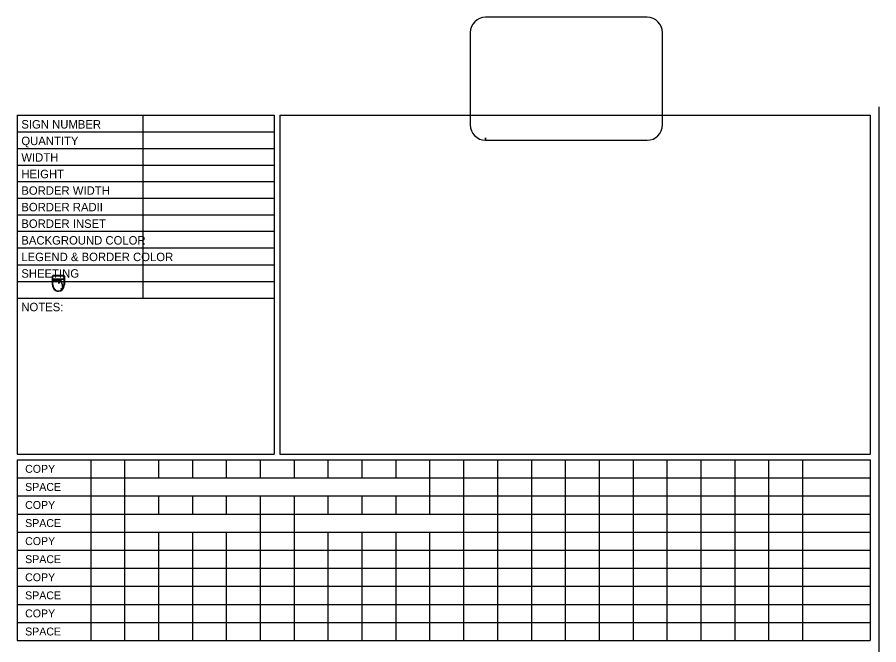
# Model space of a CAD drawing. Extents: x 10268197 to 10268511, y 2141503 to 2142677.
# Drawn here: x 10268318.5 to 10268394.7, y 2142322.7 to 2142378.2 of the extents above; entities that cross this region are included whole.
import ezdxf

# ---------------------------------------------------------------- set-up
doc = ezdxf.new("R2010")
doc.units = 0
for name, color, linetype in [('GSColorFill', 7, 'Continuous'), ('SheetBorder_dp', 7, 'Continuous'), ('SumBoxLines_dp', 7, 'Continuous'), ('SumBoxLinesMin_dp', 7, 'Continuous'), ('TextMisc', 7, 'Continuous')]:
    doc.layers.add(name, color=color, linetype=linetype)

msp = doc.modelspace()

# ---------------------------------------------------------------- linework, layer by layer
at = {"layer": 'GSColorFill'}
for p, q in [((10268374.225, 2142378.212), (10268359.932, 2142378.212)), ((10268358.571, 2142376.851), (10268358.571, 2142368.684)), ((10268375.587, 2142368.684), (10268375.587, 2142376.851)), ((10268359.932, 2142367.322), (10268359.932, 2142367.549)), ((10268359.934, 2142367.549), (10268359.934, 2142367.322)), ((10268359.934, 2142367.322), (10268374.225, 2142367.322))]:
    msp.add_line(p, q, dxfattribs=at)
for points in [[(10268321.597, 2142355.303), (10268321.597, 2142354.516)], [(10268321.597, 2142354.516), (10268321.597, 2142355.303)], [(10268321.613, 2142355.301), (10268321.613, 2142354.516)], [(10268322.615, 2142355.299), (10268322.615, 2142355.033), (10268321.635, 2142355.033), (10268321.635, 2142355.299)], [(10268321.635, 2142354.516), (10268321.635, 2142355.009), (10268322.615, 2142355.009), (10268322.615, 2142354.516)], [(10268322.595, 2142355.361), (10268321.655, 2142355.361)], [(10268321.655, 2142355.361), (10268322.595, 2142355.361)], [(10268321.658, 2142355.32), (10268322.125, 2142355.32), (10268322.125, 2142355.344), (10268321.656, 2142355.344)], [(10268321.684, 2142354.957), (10268321.685, 2142354.955)], [(10268321.972, 2142354.905), (10268322.247, 2142354.873)], [(10268322.268, 2142354.895), (10268321.98, 2142354.928)], [(10268322.594, 2142355.344), (10268322.125, 2142355.344), (10268322.125, 2142355.32), (10268322.593, 2142355.32)], [(10268322.318, 2142354.895), (10268322.33, 2142354.891)], [(10268322.334, 2142354.914), (10268322.325, 2142354.918)], [(10268322.637, 2142354.516), (10268322.637, 2142355.301)], [(10268322.654, 2142354.516), (10268322.654, 2142355.303)], [(10268322.654, 2142355.303), (10268322.654, 2142354.516)], [(10268321.71, 2142354.881), (10268321.711, 2142354.881)], [(10268321.712, 2142354.881), (10268321.713, 2142354.882)], [(10268322.169, 2142354.653), (10268322.189, 2142354.662)], [(10268322.284, 2142354.866), (10268322.282, 2142354.868)], [(10268322.309, 2142354.869), (10268322.31, 2142354.871)], [(10268322.349, 2142354.188), (10268322.328, 2142354.183)], [(10268322.337, 2142354.865), (10268322.359, 2142354.759)], [(10268322.381, 2142354.764), (10268322.358, 2142354.871)], [(10268322.387, 2142354.168), (10268322.377, 2142354.164)], [(10268322.385, 2142354.142), (10268322.402, 2142354.149)], [(10268322.394, 2142354.692), (10268322.405, 2142354.672)], [(10268322.425, 2142354.683), (10268322.414, 2142354.702)], [(10268322.417, 2142354.637), (10268322.444, 2142354.599)], [(10268322.462, 2142354.612), (10268322.434, 2142354.652)], [(10268322.451, 2142354.57), (10268322.461, 2142354.525)], [(10268322.482, 2142354.53), (10268322.472, 2142354.575)], [(10268322.125, 2142353.969), (10268322.125, 2142353.993)], [(10268322.125, 2142353.993), (10268322.125, 2142353.969), (10268322.125, 2142353.969)], [(10268322.125, 2142353.952), (10268322.125, 2142353.952)], [(10268322.125, 2142353.952), (10268322.125, 2142353.952)], [(10268322.125, 2142353.952), (10268322.125, 2142353.952)]]:
    msp.add_lwpolyline(points, dxfattribs=at)
for centre, start, end in [((10268359.932, 2142376.851), 90, 180), ((10268374.225, 2142376.851), 0, 90), ((10268359.932, 2142368.684), 180, 270), ((10268374.225, 2142368.684), 270, 0)]:
    msp.add_arc(centre, 1.361, start, end, dxfattribs=at)
for centre, major_axis, start_param, end_param in [((10268321.662, 2142355.291), (0, 0.0703), 0.098213, 1.408003), ((10268321.662, 2142355.291), (0, 0.0705), 0.098082, 1.408221), ((10268321.662, 2142355.291), (0, 0.0529), 0.11327, 1.383001), ((10268321.662, 2142355.291), (0, 0.0294), 0.152033, 1.318544), ((10268322.03, 2142354.81), (0, 0.418), 1.148552, 1.171978), ((10268321.671, 2142354.972), (0, 0.00205), 1.350308, 3.382945), ((10268321.672, 2142354.967), (0, 0.0033), 5.257186, 6.472249), ((10268321.653, 2142354.998), (0, 0.026), 4.051262, 4.587994), ((10268321.635, 2142354.936), (0, 0.0535), 5.170612, 5.366939), ((10268322.102, 2142358.792), (0, 3.824), 3.0228, 3.102998), ((10268321.681, 2142354.96), (0, 0.00167), 1.876358, 3.458947), ((10268321.691, 2142354.895), (0, 0.0123), 0.633597, 2.648042), ((10268321.682, 2142354.957), (0, 0.0023), 5.006675, 6.675737), ((10268321.688, 2142354.956), (0, 0.00328), 1.878733, 3.108176), ((10268321.682, 2142354.91), (0, 0.00646), 3.672662, 4.871849), ((10268321.687, 2142354.944), (0, 0.00855), 5.256742, 6.115579), ((10268321.781, 2142354.908), (0, 0.0999), 1.186151, 1.539742), ((10268321.691, 2142354.946), (0, 0.00333), 4.486807, 5.309085), ((10268321.687, 2142354.944), (0, 0.032), 5.272311, 5.523753), ((10268322.102, 2142358.792), (0, 3.848), 3.031956, 3.0986), ((10268321.781, 2142354.908), (0, 0.0764), 1.174629, 1.522814), ((10268321.682, 2142354.91), (0, 0.03), 4.660636, 4.76546), ((10268321.921, 2142355.496), (0, 0.629), 2.775496, 2.836), ((10268321.691, 2142354.946), (0, 0.0268), 4.38027, 5.281838), ((10268321.759, 2142354.976), (0, 0.081), 2.935797, 3.111869), ((10268321.692, 2142354.343), (0, 0.556), 6.084521, 6.158258), ((10268321.979, 2142354.965), (0, 0.0374), 2.044108, 2.116391), ((10268321.994, 2142354.948), (0, 0.0489), 1.626511, 2.63302), ((10268321.954, 2142354.964), (0, 0.012), 4.739475, 5.22955), ((10268321.979, 2142354.965), (0, 0.0139), 1.562078, 2.226686), ((10268321.964, 2142354.951), (0, 0.00667), 4.461638, 5.646624), ((10268321.994, 2142354.948), (0, 0.0254), 1.523898, 2.474336), ((10268322.276, 2142354.893), (0, 0.00913), 1.352418, 2.01063), ((10268322.321, 2142354.908), (0, 0.0351), 1.15727, 1.990189), ((10268322.292, 2142354.925), (0, 0.00308), 2.554355, 4.582696), ((10268322.273, 2142354.888), (0, 0.0194), 4.289312, 5.031813), ((10268322.303, 2142354.922), (0, 0.00883), 0.407393, 1.224717), ((10268322.301, 2142354.926), (0, 0.00399), 5.525274, 6.621403), ((10268322.328, 2142354.956), (0, 0.0373), 2.364476, 2.623448), ((10268322.312, 2142354.927), (0, 0.0037), 2.763735, 3.701166), ((10268322.273, 2142354.888), (0, 0.0429), 4.289312, 4.979338), ((10268322.319, 2142354.904), (0, 0.00845), 2.088134, 3.055358), ((10268322.315, 2142354.921), (0, 0.0032), 5.726467, 6.786368), ((10268322.309, 2142354.909), (0, 0.0168), 5.307679, 5.799127), ((10268322.32, 2142354.887), (0, 0.0308), 6.107601, 6.199828), ((10268322.338, 2142354.938), (0, 0.0241), 2.956314, 3.451659), ((10268322.347, 2142354.906), (0, 0.00977), 4.497594, 6.497324), ((10268322.419, 2142354.892), (0, 0.0684), 1.39821, 1.880074), ((10268322.589, 2142355.291), (0, 0.0294), 4.964641, 6.131152), ((10268322.589, 2142355.291), (0, 0.0529), 4.900184, 6.169915), ((10268322.589, 2142355.291), (0, 0.0703), 4.875182, 6.184972), ((10268322.589, 2142355.291), (0, 0.0705), 4.874965, 6.185103), ((10268322.125, 2142354.516), (0, 0.564), 1.570796, 3.141593), ((10268322.125, 2142354.516), (0, 0.564), 1.570796, 3.141593), ((10268322.125, 2142354.516), (0, 0.546), 1.570796, 3.141593), ((10268322.125, 2142354.516), (0, 0.523), 1.570796, 3.141593), ((10268321.696, 2142354.92), (0, 0.0377), 2.867281, 3.188718), ((10268321.695, 2142354.809), (0, 0.0733), 6.061742, 6.254182), ((10268321.711, 2142354.881), (0, 0.000638), 2.840072, 4.276704), ((10268321.713, 2142354.882), (0, 0.000524), 5.987968, 7.518423), ((10268321.921, 2142355.496), (0, 0.652), 2.795567, 2.837701), ((10268321.759, 2142354.976), (0, 0.105), 2.923962, 3.100366), ((10268321.692, 2142354.343), (0, 0.533), 6.086214, 6.156313), ((10268321.803, 2142354.918), (0, 0.0544), 2.874985, 3.359529), ((10268321.803, 2142354.918), (0, 0.0309), 2.852504, 3.366789), ((10268321.824, 2142354.81), (0, 0.0792), 6.040706, 6.480942), ((10268321.824, 2142354.81), (0, 0.0557), 6.026184, 6.476458), ((10268321.812, 2142354.704), (0, 0.161), 5.697067, 6.119013), ((10268321.812, 2142354.704), (0, 0.185), 5.684781, 6.113431), ((10268322.014, 2142354.969), (0, 0.181), 2.375, 2.467209), ((10268321.923, 2142354.808), (0, 0.0255), 0.964156, 2.090382), ((10268321.907, 2142354.797), (0, 0.00569), 1.939097, 3.308145), ((10268321.905, 2142354.822), (0, 0.00159), 5.485297, 7.704353), ((10268321.904, 2142354.82), (0, 0.0041), 4.221459, 5.929721), ((10268321.927, 2142354.812), (0, 0.0215), 1.284916, 1.908092), ((10268321.905, 2142354.816), (0, 0.0121), 4.628672, 6.022596), ((10268321.911, 2142354.807), (0, 0.00423), 2.162887, 4.05091), ((10268321.893, 2142354.894), (0, 0.104), 3.297928, 3.510473), ((10268322.014, 2142354.969), (0, 0.157), 2.362414, 2.445308), ((10268321.894, 2142354.813), (0, 0.0234), 4.312458, 4.790361), ((10268321.905, 2142354.816), (0, 0.0356), 4.927168, 5.844494), ((10268321.938, 2142354.774), (0, 0.0259), 6.114599, 6.726558), ((10268321.949, 2142354.913), (0, 0.09), 3.002553, 3.788583), ((10268321.949, 2142354.913), (0, 0.113), 3.077286, 3.764777), ((10268322.014, 2142354.812), (0, 0.0327), 0.291413, 0.478416), ((10268322.03, 2142354.83), (0, 0.0298), 1.091914, 1.118585), ((10268322.04, 2142354.826), (0, 0.041), 6.01566, 7.397045), ((10268322.014, 2142354.812), (0, 0.00922), 5.412655, 6.623003), ((10268322.029, 2142354.824), (0, 0.0104), 2.169624, 2.636557), ((10268322.03, 2142354.83), (0, 0.00627), 1.057989, 2.418777), ((10268322.026, 2142354.817), (0, 0.00291), 2.447997, 4.324956), ((10268322.04, 2142354.826), (0, 0.0175), 5.90331, 7.414322), ((10268322.022, 2142354.82), (0, 0.00757), 4.18924, 5.624255), ((10268322.05, 2142354.847), (0, 0.00632), 2.333666, 3.623187), ((10268322.057, 2142354.838), (0, 0.0282), 6.008573, 6.53107), ((10268322.057, 2142354.838), (0, 0.00472), 6.020224, 7.210209), ((10268322.033, 2142354.75), (0, 0.0962), 5.382216, 5.999852), ((10268322.033, 2142354.75), (0, 0.12), 5.371864, 6.001104), ((10268322.032, 2142354.762), (0, 0.0905), 5.020599, 5.276447), ((10268322.143, 2142354.806), (0, 0.0366), 2.049296, 2.415522), ((10268322.106, 2142354.763), (0, 0.0216), 4.723898, 5.514452), ((10268322.032, 2142354.762), (0, 0.114), 5.043581, 5.287393), ((10268322.125, 2142354.516), (0, 0.546), 3.14161, 4.712389), ((10268322.125, 2142354.516), (0, 0.523), 3.141611, 4.712389), ((10268322.125, 2142354.516), (0, 0.564), 3.141609, 4.712389), ((10268322.125, 2142354.516), (0, 0.564), 3.141609, 4.712389), ((10268322.213, 2142354.773), (0, 0.0926), 1.679569, 1.877594), ((10268322.148, 2142354.753), (0, 0.0211), 1.926422, 2.617636), ((10268322.143, 2142354.806), (0, 0.0132), 2.155604, 2.437858), ((10268322.106, 2142354.763), (0, 0.0451), 4.755633, 5.530169), ((10268322.119, 2142354.704), (0, 0.0371), 4.912404, 5.681954), ((10268322.213, 2142354.773), (0, 0.0691), 1.691953, 1.850237), ((10268322.119, 2142354.704), (0, 0.0606), 4.870438, 5.69492), ((10268322.197, 2142354.713), (0, 0.0466), 1.603254, 2.056889), ((10268322.09, 2142354.654), (0, 0.0815), 4.999681, 5.181626), ((10268322.17, 2142354.664), (0, 0.00829), 1.147713, 2.022718), ((10268322.152, 2142354.673), (0, 0.0125), 4.286383, 5.097358), ((10268322.152, 2142354.645), (0, 0.0191), 5.101976, 5.610981), ((10268322.197, 2142354.713), (0, 0.0231), 1.542583, 2.06345), ((10268322.09, 2142354.654), (0, 0.105), 5.008447, 5.183955), ((10268322.152, 2142354.673), (0, 0.036), 4.58555, 5.059156), ((10268322.152, 2142354.645), (0, 0.0426), 5.101976, 5.271031), ((10268322.272, 2142354.871), (0, 0.0263), 1.495786, 3.039166), ((10268322.188, 2142354.874), (0, 0.0869), 4.732247, 4.878022), ((10268322.262, 2142354.875), (0, 0.00805), 4.379744, 4.814874), ((10268322.272, 2142354.871), (0, 0.00285), 1.109885, 3.045896), ((10268322.277, 2142354.926), (0, 0.0809), 3.036263, 3.109566), ((10268322.277, 2142354.926), (0, 0.0574), 3.035408, 3.204096), ((10268322.285, 2142354.866), (0, 0.0242), 2.680355, 4.018837), ((10268322.28, 2142354.865), (0, 0.00354), 5.664697, 6.296132), ((10268322.285, 2142354.866), (0, 0.000707), 2.226104, 4.018837), ((10268322.282, 2142354.868), (0, 0.00364), 4.143687, 4.652253), ((10268322.32, 2142354.862), (0, 0.0367), 1.060493, 1.42239), ((10268322.293, 2142354.86), (0, 0.0137), 3.974032, 4.188492), ((10268322.282, 2142354.868), (0, 0.0271), 4.143687, 4.589576), ((10268322.32, 2142354.862), (0, 0.0132), 1.060493, 1.394015), ((10268322.377, 2142354.195), (0, 0.0543), 1.791653, 2.340122), ((10268322.338, 2142354.938), (0, 0.0476), 2.956314, 3.025542), ((10268322.419, 2142354.892), (0, 0.0919), 1.581121, 1.86815), ((10268322.351, 2142354.171), (0, 0.0176), 2.46822, 2.97436), ((10268322.345, 2142354.141), (0, 0.0125), 5.314558, 6.021061), ((10268322.377, 2142354.195), (0, 0.0308), 1.791653, 2.227493), ((10268322.345, 2142354.141), (0, 0.036), 5.376414, 6.007417), ((10268322.362, 2142354.15), (0, 0.00715), 1.799944, 2.906604), ((10268322.41, 2142354.769), (0, 0.0552), 1.756608, 2.347825), ((10268322.373, 2142354.174), (0, 0.0338), 2.704263, 3.531223), ((10268322.373, 2142354.174), (0, 0.0103), 2.98946, 3.543074), ((10268322.302, 2142354.661), (0, 0.103), 5.016392, 5.452977), ((10268322.41, 2142354.769), (0, 0.0317), 1.744904, 2.358794), ((10268322.409, 2142354.15), (0, 0.0301), 5.78233, 7.207903), ((10268322.302, 2142354.661), (0, 0.126), 5.037317, 5.457008), ((10268322.401, 2142354.151), (0, 0.00205), 3.416847, 4.470626), ((10268322.409, 2142354.15), (0, 0.00661), 5.753294, 7.753434), ((10268322.39, 2142354.664), (0, 0.0174), 4.762949, 5.1373), ((10268322.45, 2142354.668), (0, 0.0467), 1.627095, 2.292298), ((10268322.439, 2142354.21), (0, 0.0607), 2.662545, 2.881892), ((10268322.439, 2142354.21), (0, 0.0373), 2.671152, 2.787623), ((10268322.426, 2142354.162), (0, 0.0111), 2.983509, 3.299677), ((10268322.39, 2142354.664), (0, 0.0409), 4.76521, 5.169372), ((10268322.485, 2142353.84), (0, 0.34), 0.131385, 0.184159), ((10268322.485, 2142353.84), (0, 0.317), 0.127189, 0.195375), ((10268322.45, 2142354.668), (0, 0.0232), 1.628927, 2.328642), ((10268322.435, 2142354.21), (0, 0.0339), 3.405622, 3.421225), ((10268322.424, 2142354.584), (0, 0.0255), 4.794307, 5.332356), ((10268322.483, 2142354.16), (0, 0.0455), 1.014577, 1.160734), ((10268322.491, 2142354.194), (0, 0.049), 1.41458, 1.781645), ((10268322.519, 2142354.188), (0, 0.0794), 0.819897, 1.393572), ((10268322.435, 2142354.21), (0, 0.0574), 3.374432, 3.63571), ((10268322.543, 2142354.595), (0, 0.102), 1.656393, 1.820063), ((10268322.457, 2142354.165), (0, 0.00633), 3.821556, 4.442761), ((10268322.519, 2142354.535), (0, 0.0626), 1.731328, 2.298174), ((10268322.424, 2142354.584), (0, 0.0489), 4.795389, 5.336514), ((10268322.483, 2142354.16), (0, 0.022), 0.796146, 1.41392), ((10268322.485, 2142354.223), (0, 0.0286), 0.515561, 0.875133), ((10268322.491, 2142354.194), (0, 0.0255), 1.423525, 1.922114), ((10268322.519, 2142354.188), (0, 0.0559), 0.804456, 1.388824), ((10268322.46, 2142354.181), (0, 0.0105), 4.101497, 5.116348), ((10268322.543, 2142354.595), (0, 0.0784), 1.65682, 1.82178), ((10268322.641, 2142354.268), (0, 0.181), 1.336714, 1.678883), ((10268322.473, 2142354.492), (0, 0.00243), 4.321398, 5.522959), ((10268321.814, 2142354.399), (0, 0.711), 4.587168, 4.842218), ((10268322.519, 2142354.535), (0, 0.0391), 1.711025, 2.288429), ((10268322.485, 2142354.223), (0, 0.00515), 0.505292, 0.959827), ((10268322.481, 2142354.231), (0, 0.00426), 3.85142, 4.724901), ((10268322.505, 2142354.233), (0, 0.0223), 1.391226, 1.671625), ((10268322.492, 2142354.243), (0, 0.00793), 0.616902, 1.430067), ((10268322.21, 2142354.259), (0, 0.294), 4.638315, 4.661489), ((10268322.49, 2142354.223), (0, 0.00329), 0.723397, 2.164197), ((10268322.487, 2142354.244), (0, 0.0061), 5.021411, 6.053889), ((10268322.479, 2142354.233), (0, 0.0123), 4.104143, 4.720111), ((10268322.49, 2142354.222), (0, 0.00233), 1.92196, 4.222615), ((10268322.647, 2142354.208), (0, 0.169), 1.349215, 1.424914), ((10268322.473, 2142354.492), (0, 0.0259), 4.682902, 5.462261), ((10268322.641, 2142354.268), (0, 0.158), 1.328956, 1.760151), ((10268322.472, 2142354.235), (0, 0.0249), 4.100878, 4.619123), ((10268322.479, 2142354.236), (0, 0.0177), 4.523068, 4.807624), ((10268321.814, 2142354.399), (0, 0.735), 4.585352, 4.838269)]:
    msp.add_ellipse(centre, major_axis=major_axis, ratio=0.937499, start_param=start_param, end_param=end_param, dxfattribs=at)
at = {"layer": 'SheetBorder_dp'}
msp.add_line((10268394.73, 2142370.281), (10268394.73, 2142274.281), dxfattribs=at)
at = {"layer": 'SumBoxLines_dp'}
for p, q in [((10268318.48, 2142369.531), (10268318.48, 2142339.531)), ((10268318.48, 2142369.531), (10268341.23, 2142369.531)), ((10268329.598, 2142369.527), (10268329.598, 2142353.344)), ((10268341.23, 2142369.531), (10268341.23, 2142339.531)), ((10268341.73, 2142369.531), (10268341.73, 2142339.531)), ((10268341.73, 2142369.531), (10268393.98, 2142369.531)), ((10268393.98, 2142369.531), (10268393.98, 2142339.531)), ((10268318.48, 2142368.065), (10268341.23, 2142368.065)), ((10268318.48, 2142366.59), (10268341.23, 2142366.59)), ((10268318.48, 2142365.124), (10268341.23, 2142365.124)), ((10268318.48, 2142363.658), (10268341.23, 2142363.658)), ((10268318.48, 2142362.192), (10268341.23, 2142362.192)), ((10268318.48, 2142360.726), (10268341.23, 2142360.726)), ((10268318.48, 2142359.261), (10268341.23, 2142359.261)), ((10268318.48, 2142357.785), (10268341.23, 2142357.785)), ((10268318.48, 2142356.28), (10268341.23, 2142356.28)), ((10268318.479, 2142354.812), (10268341.23, 2142354.812)), ((10268318.478, 2142353.344), (10268341.229, 2142353.344)), ((10268318.48, 2142339.531), (10268341.23, 2142339.531)), ((10268318.48, 2142339.031), (10268393.98, 2142339.031)), ((10268318.48, 2142339.031), (10268318.48, 2142323.031)), ((10268324.98, 2142339.031), (10268324.98, 2142323.031)), ((10268327.98, 2142339.031), (10268327.98, 2142323.031)), ((10268330.98, 2142339.031), (10268330.98, 2142337.431)), ((10268333.98, 2142339.031), (10268333.98, 2142337.431)), ((10268336.98, 2142339.031), (10268336.98, 2142337.431)), ((10268339.98, 2142339.031), (10268339.98, 2142337.431)), ((10268341.73, 2142339.531), (10268393.98, 2142339.531)), ((10268342.98, 2142339.031), (10268342.98, 2142337.431)), ((10268345.98, 2142339.031), (10268345.98, 2142337.431)), ((10268348.98, 2142339.031), (10268348.98, 2142337.431)), ((10268351.98, 2142339.031), (10268351.98, 2142337.431)), ((10268354.98, 2142339.031), (10268354.98, 2142337.431)), ((10268357.98, 2142339.031), (10268357.98, 2142337.431)), ((10268360.98, 2142339.031), (10268360.98, 2142335.831)), ((10268363.98, 2142339.031), (10268363.98, 2142335.831)), ((10268366.98, 2142339.031), (10268366.98, 2142335.831)), ((10268369.98, 2142339.031), (10268369.98, 2142335.831)), ((10268372.98, 2142339.031), (10268372.98, 2142337.431)), ((10268375.98, 2142339.031), (10268375.98, 2142337.431)), ((10268378.98, 2142339.031), (10268378.98, 2142337.431)), ((10268381.98, 2142339.031), (10268381.98, 2142337.431)), ((10268384.98, 2142339.031), (10268384.98, 2142337.431)), ((10268387.98, 2142339.031), (10268387.98, 2142337.431)), ((10268393.98, 2142339.031), (10268393.98, 2142323.031)), ((10268354.98, 2142337.431), (10268354.98, 2142334.231)), ((10268357.98, 2142337.431), (10268357.98, 2142332.631)), ((10268372.98, 2142337.431), (10268372.98, 2142323.031)), ((10268375.98, 2142337.431), (10268375.98, 2142323.031)), ((10268378.98, 2142337.431), (10268378.98, 2142331.031)), ((10268381.98, 2142337.431), (10268381.98, 2142331.031)), ((10268384.98, 2142337.431), (10268384.98, 2142331.031)), ((10268387.98, 2142337.431), (10268387.98, 2142323.031)), ((10268318.48, 2142335.831), (10268393.98, 2142335.831)), ((10268330.98, 2142335.831), (10268330.98, 2142334.231)), ((10268333.98, 2142335.831), (10268333.98, 2142334.231)), ((10268336.98, 2142335.831), (10268336.98, 2142334.231)), ((10268339.98, 2142335.831), (10268339.98, 2142332.631)), ((10268342.98, 2142335.831), (10268342.98, 2142332.631)), ((10268345.98, 2142335.831), (10268345.98, 2142334.231)), ((10268348.98, 2142335.831), (10268348.98, 2142334.231)), ((10268351.98, 2142335.831), (10268351.98, 2142334.231)), ((10268360.98, 2142335.831), (10268360.98, 2142332.631)), ((10268363.98, 2142335.831), (10268363.98, 2142332.631)), ((10268366.98, 2142335.831), (10268366.98, 2142331.031)), ((10268369.98, 2142335.831), (10268369.98, 2142331.031)), ((10268318.48, 2142332.631), (10268393.98, 2142332.631)), ((10268330.98, 2142332.631), (10268330.98, 2142329.431)), ((10268333.98, 2142332.631), (10268333.98, 2142329.431)), ((10268336.98, 2142332.631), (10268336.98, 2142329.431)), ((10268339.98, 2142332.631), (10268339.98, 2142329.431)), ((10268342.98, 2142332.631), (10268342.98, 2142329.431)), ((10268345.98, 2142332.631), (10268345.98, 2142329.431)), ((10268348.98, 2142332.631), (10268348.98, 2142329.431)), ((10268351.98, 2142332.631), (10268351.98, 2142329.431)), ((10268354.98, 2142332.631), (10268354.98, 2142323.031)), ((10268357.98, 2142332.631), (10268357.98, 2142323.031)), ((10268360.98, 2142332.631), (10268360.98, 2142323.031)), ((10268363.98, 2142332.631), (10268363.98, 2142323.031)), ((10268366.98, 2142331.031), (10268366.98, 2142323.031)), ((10268369.98, 2142331.031), (10268369.98, 2142323.031)), ((10268378.98, 2142331.031), (10268378.98, 2142323.031)), ((10268381.98, 2142331.031), (10268381.98, 2142323.031)), ((10268384.98, 2142331.031), (10268384.98, 2142323.031)), ((10268318.48, 2142329.431), (10268393.98, 2142329.431)), ((10268330.98, 2142329.431), (10268330.98, 2142323.031)), ((10268333.98, 2142329.431), (10268333.98, 2142323.031)), ((10268336.98, 2142329.431), (10268336.98, 2142326.231)), ((10268339.98, 2142329.431), (10268339.98, 2142326.231)), ((10268342.98, 2142329.431), (10268342.98, 2142326.231)), ((10268345.98, 2142329.431), (10268345.98, 2142326.231)), ((10268348.98, 2142329.431), (10268348.98, 2142323.031)), ((10268351.98, 2142329.431), (10268351.98, 2142323.031)), ((10268318.48, 2142326.231), (10268393.98, 2142326.231)), ((10268336.98, 2142326.231), (10268336.98, 2142323.031)), ((10268339.98, 2142326.231), (10268339.98, 2142323.031)), ((10268342.98, 2142326.231), (10268342.98, 2142323.031)), ((10268345.98, 2142326.231), (10268345.98, 2142323.031)), ((10268318.48, 2142323.031), (10268393.98, 2142323.031))]:
    msp.add_line(p, q, dxfattribs=at)
at = {"layer": 'SumBoxLinesMin_dp'}
for p, q in [((10268318.48, 2142337.431), (10268393.98, 2142337.431)), ((10268318.48, 2142334.231), (10268393.98, 2142334.231)), ((10268318.48, 2142331.031), (10268393.98, 2142331.031)), ((10268318.48, 2142327.831), (10268393.98, 2142327.831)), ((10268318.48, 2142324.631), (10268393.98, 2142324.631))]:
    msp.add_line(p, q, dxfattribs=at)

# ---------------------------------------------------------------- texts
at = {"layer": 'TextMisc'}
for s, height, p in [('SIGN NUMBER', 0.74756, (10268318.842, 2142368.358)), ('QUANTITY', 0.7476, (10268318.842, 2142366.892)), ('WIDTH', 0.7476, (10268318.842, 2142365.427)), ('HEIGHT', 0.7476, (10268318.842, 2142363.961)), ('BORDER WIDTH', 0.74756, (10268318.842, 2142362.495)), ('BORDER RADII', 0.74756, (10268318.842, 2142361.029)), ('BORDER INSET', 0.74756, (10268318.842, 2142359.563)), ('BACKGROUND COLOR', 0.74756, (10268318.841, 2142358.086)), ('LEGEND & BORDER COLOR', 0.74756, (10268318.841, 2142356.62)), ('SHEETING', 0.7476, (10268318.841, 2142355.154)), ('NOTES:', 0.7476, (10268318.841, 2142352.183)), ('COPY', 0.7, (10268319.18, 2142337.881)), ('SPACE', 0.7, (10268319.18, 2142336.281)), ('COPY', 0.7, (10268319.18, 2142334.681)), ('SPACE', 0.7, (10268319.18, 2142333.081)), ('COPY', 0.7, (10268319.18, 2142331.481)), ('SPACE', 0.7, (10268319.18, 2142329.881)), ('COPY', 0.7, (10268319.18, 2142328.281)), ('SPACE', 0.7, (10268319.18, 2142326.681)), ('COPY', 0.7, (10268319.18, 2142325.081)), ('SPACE', 0.7, (10268319.18, 2142323.481))]:
    msp.add_text(s, height=height, dxfattribs=at).set_placement(p)

doc.saveas('drawing.dxf')
